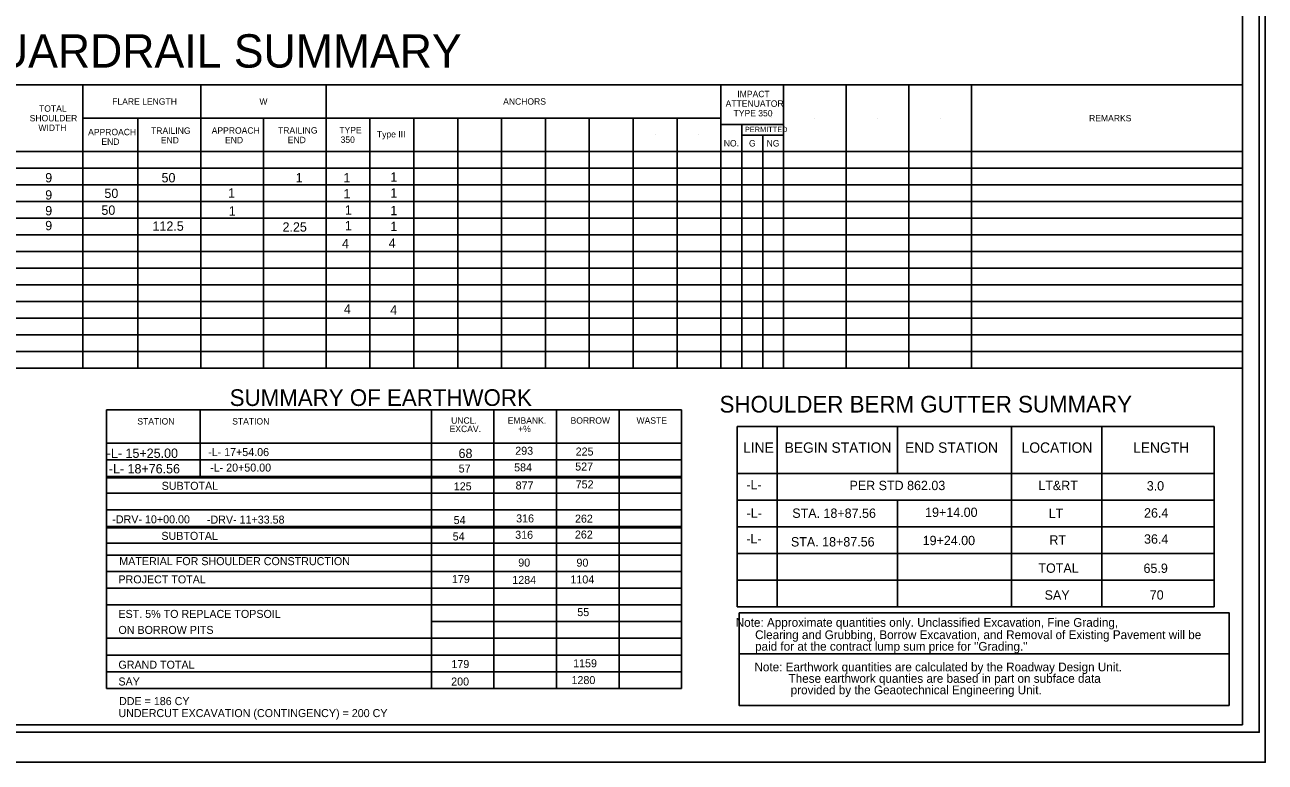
# Model space of a CAD drawing. Extents: x 2109603 to 2111999, y 434786 to 437408.
# Drawn here: x 2110437 to 2111367, y 436108 to 436660 of the extents above; entities that cross this region are included whole.
import ezdxf

# ---------------------------------------------------------------- set-up
doc = ezdxf.new("R2010")
doc.units = 0
for name, color, linetype in [('Old_Level_1', 7, 'Continuous'), ('Prop Grid Mask', 7, 'Continuous'), ('Prop XSC Text', 7, 'Continuous'), ('Sheet Cutting Line CELL', 7, 'Continuous'), ('Sheet Pipe Summary CELL', 7, 'Continuous'), ('Sheet Plot Border Inside CELL', 7, 'Continuous'), ('Sheet Plot Border Outside CELL', 7, 'Continuous'), ('Sheet Summary Combination CELL', 7, 'Continuous'), ('Sheet Summary Combination Grid CELL', 7, 'Continuous'), ('Sheet Summary Earthwork CELL', 7, 'Continuous'), ('Sheet Summary Guardrail CELL', 7, 'Continuous')]:
    doc.layers.add(name, color=color, linetype=linetype)

msp = doc.modelspace()

# ---------------------------------------------------------------- linework, layer by layer
at = {"layer": 'Prop Grid Mask'}
for points in [[(2110972.38, 436219.6), (2111339.74, 436219.6), (2111339.74, 436188.87), (2110972.38, 436188.87)], [(2110972.38, 436188.87), (2111339.74, 436188.87), (2111339.74, 436150.24), (2110972.38, 436150.24)]]:
    msp.add_lwpolyline(points, close=True, dxfattribs=at)
at = {"layer": 'Sheet Cutting Line CELL'}
msp.add_line((2109682.84, 436107.62), (2111366.84, 436107.62), dxfattribs=at)
at = {"layer": 'Sheet Pipe Summary CELL'}
msp.add_line((2109849.84, 436135.62), (2111349.84, 436135.62), dxfattribs=at)
msp.add_lwpolyline([(2111349.84, 436135.62), (2111349.84, 437182.62), (2109849.84, 437182.62), (2109849.84, 436135.62)], dxfattribs=at)
at = {"layer": 'Sheet Plot Border Inside CELL'}
msp.add_lwpolyline([(2109695.84, 436130.07), (2111362.34, 436130.07), (2111362.34, 437185.17), (2109695.84, 437185.17)], close=True, dxfattribs=at)
at = {"layer": 'Sheet Plot Border Outside CELL'}
msp.add_lwpolyline([(2109682.84, 436107.62), (2111366.84, 436107.62), (2111366.84, 437207.62), (2109682.84, 437207.62)], close=True, dxfattribs=at)
at = {"layer": 'Sheet Summary Combination CELL'}
for p, q in [((2110592.35, 436371.71), (2110592.35, 436371.71)), ((2110598.6, 436371.61), (2110598.6, 436371.61)), ((2110607.65, 436371.81), (2110607.65, 436371.81)), ((2110613.25, 436371.71), (2110613.25, 436371.71))]:
    msp.add_line(p, q, dxfattribs=at)
at = {"layer": 'Sheet Summary Combination Grid CELL'}
for p, q in [((2110498, 436371.76), (2110929.25, 436371.76)), ((2110498, 436371.76), (2110498, 436162.97)), ((2110568.35, 436371.76), (2110568.35, 436320.76)), ((2110741.65, 436371.76), (2110741.65, 436237.97)), ((2110788.55, 436371.76), (2110788.55, 436162.97)), ((2110835.45, 436371.76), (2110835.45, 436162.97)), ((2110882.35, 436371.76), (2110882.35, 436162.97)), ((2110929.25, 436371.76), (2110929.25, 436162.97)), ((2110498, 436346.76), (2110929.25, 436346.76)), ((2110498, 436334.26), (2110929.25, 436334.26)), ((2110498, 436321.76), (2110929.25, 436321.76)), ((2110498, 436320.76), (2110929.25, 436320.76)), ((2110498, 436309.26), (2110929.25, 436309.26)), ((2110498, 436296.76), (2110929.25, 436296.76)), ((2110498, 436284.26), (2110929.25, 436284.26)), ((2110498, 436283.26), (2110929.25, 436283.26)), ((2110498, 436271.76), (2110929.25, 436271.76)), ((2110498, 436262.76), (2110929.25, 436262.76)), ((2110498, 436250.47), (2110929.25, 436250.47)), ((2110498, 436237.97), (2110929.25, 436237.97)), ((2110741.65, 436237.97), (2110741.65, 436162.97)), ((2110498, 436225.47), (2110929.25, 436225.47)), ((2110741.65, 436212.97), (2110929.25, 436212.97)), ((2110498, 436200.47), (2110929.25, 436200.47)), ((2110498, 436187.97), (2110929.25, 436187.97)), ((2110498, 436175.47), (2110929.25, 436175.47)), ((2110498, 436162.97), (2110929.25, 436162.97)), ((2110498, 436162.97), (2110929.25, 436162.97))]:
    msp.add_line(p, q, dxfattribs=at)
at = {"layer": 'Sheet Summary Earthwork CELL'}
for p, q in [((2110970.96, 436359.14), (2111328.51, 436359.14)), ((2110970.96, 436264.14), (2110970.96, 436359.14)), ((2111000.96, 436264.14), (2111000.96, 436359.14)), ((2111091.01, 436324.14), (2111091.01, 436359.14)), ((2111176.57, 436359.14), (2111176.57, 436264.14)), ((2111220.96, 436359.14), (2111320.96, 436359.14)), ((2111244.46, 436264.14), (2111244.46, 436359.14)), ((2111328.51, 436359.14), (2111328.51, 436264.14)), ((2111328.51, 436324.14), (2110970.96, 436324.14)), ((2110970.96, 436304.14), (2111328.51, 436304.14)), ((2111091.01, 436224.14), (2111091.01, 436304.14)), ((2111328.51, 436284.14), (2110970.96, 436284.14)), ((2110970.96, 436284.14), (2110970.96, 436264.14)), ((2110970.96, 436224.14), (2110970.96, 436264.14)), ((2110970.96, 436264.14), (2111328.51, 436264.14)), ((2110970.96, 436264.14), (2111328.51, 436264.14)), ((2111000.96, 436224.14), (2111000.96, 436264.14)), ((2111176.57, 436264.14), (2111176.57, 436224.14)), ((2111244.46, 436224.14), (2111244.46, 436264.14)), ((2111328.51, 436264.14), (2111328.51, 436224.14)), ((2111328.51, 436244.14), (2110970.96, 436244.14)), ((2110970.96, 436244.14), (2110970.96, 436224.14)), ((2111328.51, 436224.14), (2110970.96, 436224.14))]:
    msp.add_line(p, q, dxfattribs=at)
at = {"layer": 'Sheet Summary Guardrail CELL'}
for p, q in [((2109849.84, 436615.39), (2111349.84, 436615.39)), ((2110480.34, 436615.39), (2110480.34, 436402.89)), ((2110568.64, 436615.39), (2110568.64, 436402.89)), ((2110662.64, 436615.39), (2110662.64, 436402.89)), ((2110958.74, 436615.39), (2110958.74, 436402.89)), ((2111005.74, 436615.39), (2111005.74, 436402.89)), ((2111052.74, 436615.39), (2111052.74, 436402.89)), ((2111099.74, 436615.39), (2111099.74, 436402.89)), ((2111146.74, 436615.39), (2111146.74, 436402.89)), ((2110958.74, 436590.39), (2110480.34, 436590.39)), ((2110521.64, 436590.39), (2110521.64, 436402.89)), ((2110615.64, 436590.39), (2110615.64, 436402.89)), ((2110695.54, 436590.39), (2110695.54, 436402.89)), ((2110728.44, 436590.39), (2110728.44, 436402.89)), ((2110761.34, 436590.39), (2110761.34, 436402.89)), ((2110794.24, 436590.39), (2110794.24, 436402.89)), ((2110827.14, 436590.39), (2110827.14, 436402.89)), ((2110860.04, 436590.39), (2110860.04, 436402.89)), ((2110892.94, 436590.39), (2110892.94, 436402.89)), ((2110925.84, 436590.39), (2110925.84, 436402.89)), ((2110958.74, 436585.64), (2111005.74, 436585.64)), ((2110974.39, 436585.64), (2110974.39, 436402.89)), ((2110996.84, 436590.64), (2110996.84, 436590.64)), ((2111029.24, 436590.39), (2111029.24, 436590.39)), ((2111076.24, 436590.39), (2111076.24, 436590.39)), ((2111123.24, 436590.39), (2111123.24, 436590.39)), ((2110679.09, 436577.89), (2110679.09, 436577.89)), ((2110711.49, 436578.43), (2110711.49, 436578.43)), ((2110909.39, 436577.89), (2110909.39, 436577.89)), ((2110942.29, 436577.89), (2110942.29, 436577.89)), ((2110974.39, 436577.64), (2111005.74, 436577.64)), ((2110990.04, 436577.64), (2110990.04, 436402.89)), ((2109849.84, 436565.39), (2111349.84, 436565.39)), ((2109849.84, 436552.89), (2111349.84, 436552.89)), ((2109849.84, 436540.39), (2111349.84, 436540.39)), ((2109849.84, 436527.89), (2111349.84, 436527.89)), ((2109849.84, 436515.39), (2111349.84, 436515.39)), ((2109849.84, 436502.89), (2111349.84, 436502.89)), ((2109849.84, 436490.39), (2111349.84, 436490.39)), ((2109849.84, 436477.89), (2111349.84, 436477.89)), ((2109849.84, 436465.39), (2111349.84, 436465.39)), ((2109849.84, 436452.89), (2111349.84, 436452.89)), ((2109849.84, 436440.39), (2111349.84, 436440.39)), ((2109849.84, 436427.89), (2111349.84, 436427.89)), ((2109849.84, 436415.39), (2111349.84, 436415.39)), ((2109849.84, 436402.89), (2111349.84, 436402.89))]:
    msp.add_line(p, q, dxfattribs=at)

# ---------------------------------------------------------------- texts
at = {"layer": 'Old_Level_1'}
for s, height, p in [('TYPE', 4.8, (2110672.6, 436579.06)), ('350', 4.8, (2110673.55, 436571.86)), ('9', 7, (2110452.09, 436542.24)), ('50', 7, (2110539.3, 436542.24)), ('1', 7, (2110639.85, 436542.24)), ('1', 7, (2110675.68, 436542.24)), ('1', 7, (2110710.86, 436542.79)), ('1', 7, (2110675.76, 436530.27)), ('1', 7, (2110710.86, 436530.86)), ('9', 7, (2110452.09, 436529.36)), ('9', 7, (2110452.09, 436517.51)), ('1', 7, (2110676.77, 436518.1)), ('1', 7, (2110710.86, 436517.67)), ('9', 7, (2110452.09, 436506.39)), ('1', 7, (2110676.77, 436506.37)), ('1', 7, (2110710.86, 436505.73)), ('4', 7, (2110709.67, 436493.29)), ('4', 7, (2110674.58, 436492.86)), ('4', 7, (2110676.03, 436443.87)), ('4', 7, (2110710.75, 436443.16)), ('-L-', 7, (2110977.81, 436312.09)), ('PER STD 862.03', 7, (2111055.15, 436311.57)), ('LT&RT', 7, (2111196.73, 436311.57)), ('3.0', 7, (2111278.03, 436311.28)), ('-L-', 7, (2110977.98, 436290.8)), ('STA. 18+87.56', 7, (2111012.24, 436290.78)), ('19+14.00', 7, (2111111.85, 436291.45)), ('LT', 7, (2111204.47, 436290.61)), ('26.4', 7, (2111276, 436291.01)), ('-L-', 7, (2110977.76, 436271.67)), ('19+24.00', 7, (2111110, 436270.32)), ('RT', 7, (2111205.06, 436270.67)), ('36.4', 7, (2111276, 436271.42)), ('STA. 18+87.56', 7, (2111011.23, 436269.32)), ('TOTAL', 7, (2111196.81, 436249.59)), ('65.9', 7, (2111275.61, 436249.52)), ('SAY', 7, (2111201.44, 436229.44)), ('70', 7, (2111280.29, 436229.5))]:
    msp.add_text(s, height=height, dxfattribs=at).set_placement(p)
for s, height, rotation, p in [('50', 7, 360, (2110496.48, 436530.54)), ('1', 7, 360, (2110589.19, 436530.8)), ('50', 7, 0.07789, (2110494.2, 436517.93)), ('1', 7, 360, (2110589.65, 436517.28)), ('112.5', 7, 360, (2110532.52, 436505.97)), ('2.25', 7, 0.07789, (2110630.03, 436505.31)), ('-L- 15+25.00', 7, 360, (2110498.26, 436335.73)), ('-L- 17+54.06', 6, 360, (2110574.2, 436337.09)), ('68', 7, 360, (2110761.99, 436335.62)), ('293', 6, 360, (2110804.51, 436338.07)), ('225', 6, 360, (2110849.81, 436337.5)), ('-L- 18+76.56', 7, 360, (2110499.77, 436324.1)), ('-L- 20+50.00', 6, 360, (2110575.72, 436325.46)), ('57', 6, 360, (2110762.1, 436324.76)), ('584', 6, 360, (2110803.67, 436325.61)), ('527', 6, 360, (2110849.48, 436326.23)), ('125', 6, 360, (2110758.43, 436311.4)), ('877', 6, 360, (2110804.79, 436312.08)), ('752', 6, 360, (2110849.84, 436312.87)), ('-DRV- 10+00.00', 6, 360, (2110502.37, 436286.68)), ('-DRV- 11+33.58', 6, 360, (2110573.31, 436286.47)), ('54', 6, 360, (2110758.33, 436286.12)), ('316', 6, 360, (2110805.2, 436287.36)), ('262', 6, 360, (2110849.3, 436287.18)), ('54', 6, 360, (2110757.61, 436273.85)), ('316', 6, 360, (2110804.48, 436275.09)), ('262', 6, 360, (2110849.26, 436275.27)), ('MATERIAL FOR SHOULDER CONSTRUCTION', 6, 360, (2110507.61, 436255.33)), ('90', 6, 360, (2110806.77, 436254.26)), ('90', 6, 360, (2110850.42, 436254.19)), ('PROJECT TOTAL', 6, 360, (2110506.97, 436241.66)), ('179', 6, 360, (2110757.03, 436241.88)), ('1284', 6, 360, (2110802.3, 436241.26)), ('1104', 6, 360, (2110845.88, 436241.61)), ('EST. 5% TO REPLACE TOPSOIL', 6, 360, (2110506.97, 436215.77)), ('55', 6, 360, (2110851.06, 436217.13)), ('ON BORROW PITS', 6, 360, (2110506.97, 436203.77)), ('GRAND TOTAL', 6, 360, (2110506.97, 436177.7)), ('179', 6, 360, (2110756.66, 436178.18)), ('1159', 6, 360, (2110847.93, 436178.76)), ('SAY', 6, 360, (2110506.97, 436165.12)), ('200', 6, 360, (2110756.49, 436165.09)), ('1280', 6, 360, (2110846.71, 436166.17)), ('DDE = 186 CY', 6, 360, (2110507.42, 436150.41))]:
    msp.add_text(s, height=height, rotation=rotation, dxfattribs=at).set_placement(p)
at = {"layer": 'Prop XSC Text'}
for s, p in [('     Note: Approximate quantities only. Unclassified Excavation, Fine Grading,  ', (2110957.64, 436209.11)), (' Clearing and Grubbing, Borrow Excavation, and Removal of Existing Pavement will be', (2110981.91, 436199.89)), (' paid for at the contract lump sum price for "Grading."', (2110981.89, 436191.2)), ('Note: Earthwork quantities are calculated by the Roadway Design Unit.', (2110983.87, 436175.73)), ('These earthwork quanties are based in part on subface data', (2111009.44, 436167.13)), ('provided by the Geaotechnical Engineering Unit.', (2111011.04, 436158.53))]:
    msp.add_text(s, height=6.561, rotation=360, dxfattribs=at).set_placement(p)
at = {"layer": 'Sheet Pipe Summary CELL'}
msp.add_text('Type III', height=4.8, dxfattribs=at).set_placement((2110700.79, 436575.95))
at = {"layer": 'Sheet Summary Combination CELL'}
for s, p in [('SUMMARY OF EARTHWORK', (2110590.39, 436374.64)), (' SHOULDER BERM GUTTER SUMMARY ', (2110953.06, 436369.7))]:
    msp.add_text(s, height=12.5001, rotation=0.01193, dxfattribs=at).set_placement(p)
for s, height, p in [('STATION', 4.8, (2110521.15, 436360.72)), ('STATION', 4.8, (2110592.29, 436360.74)), ('UNCL.', 4.8, (2110756.45, 436361.35)), ('EMBANK.', 4.8, (2110798.83, 436361.35)), ('BORROW', 4.8, (2110846, 436361.35)), ('WASTE', 4.8, (2110895.45, 436361.35)), ('EXCAV.', 4.8, (2110755.29, 436355.05)), ('+%', 4.8, (2110806.71, 436355.05)), ('SUBTOTAL', 6, (2110539.39, 436311.8)), ('SUBTOTAL', 6, (2110539.2, 436274.28)), ('UNDERCUT EXCAVATION (CONTINGENCY) = 200 CY', 6, (2110506.97, 436141.42))]:
    msp.add_text(s, height=height, dxfattribs=at).set_placement(p)
at = {"layer": 'Sheet Summary Earthwork CELL'}
for s, height, p in [('LINE', 7.75, (2110975.35, 436339.56)), ('BEGIN STATION', 7.7499, (2111006.51, 436339.56)), ('END STATION', 7.7499, (2111096.81, 436339.56)), ('LOCATION', 7.75, (2111184.22, 436339.56)), ('LENGTH', 7.75, (2111267.78, 436339.56))]:
    msp.add_text(s, height=height, dxfattribs=at).set_placement(p)
at = {"layer": 'Sheet Summary Guardrail CELL'}
for s, height, p in [('GUARDRAIL SUMMARY', 24.9999, (2110389.14, 436628.29)), ('FLARE LENGTH', 4.8, (2110502.29, 436600.49)), ('W', 4.8, (2110612.69, 436600.49)), ('ANCHORS', 4.8, (2110795.44, 436600.49)), ('ATTENUATOR', 4.8, (2110962.25, 436598.9)), ('IMPACT', 4.8, (2110971.05, 436606.1)), ('TOTAL', 4.8, (2110447.44, 436595.19)), ('TYPE 350', 4.8, (2110968.2, 436591.7)), ('SHOULDER', 4.8, (2110440.44, 436587.99)), ('WIDTH', 4.8, (2110446.94, 436580.79)), ('APPROACH', 4.8, (2110576.89, 436578.74)), ('TRAILING', 4.8, (2110626.64, 436578.84)), ('PERMITTED', 4, (2110976.73, 436579.94)), ('REMARKS', 4.8, (2111234.79, 436587.99)), ('APPROACH', 4.8, (2110484.24, 436577.59)), ('END', 4.8, (2110494.19, 436570.39)), ('TRAILING', 4.8, (2110531.44, 436578.64)), ('END', 4.8, (2110538.74, 436571.44)), ('END', 4.8, (2110586.89, 436571.54)), ('END', 4.8, (2110633.94, 436571.64)), ('NO.', 4.8, (2110960.86, 436569.16)), ('G', 4.8, (2110979.79, 436569.14)), ('NG', 4.8, (2110992.99, 436569.14))]:
    msp.add_text(s, height=height, rotation=360, dxfattribs=at).set_placement(p)

doc.saveas('drawing.dxf')
